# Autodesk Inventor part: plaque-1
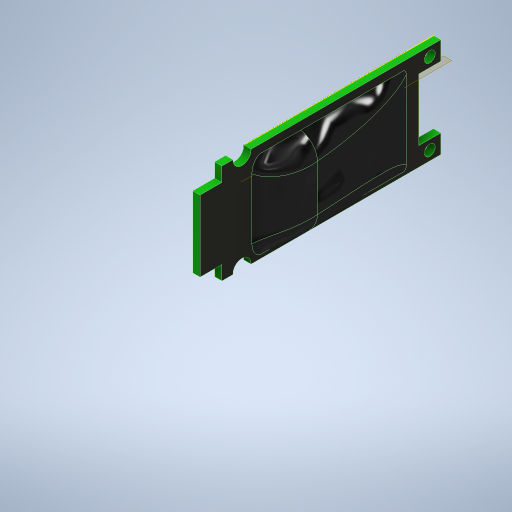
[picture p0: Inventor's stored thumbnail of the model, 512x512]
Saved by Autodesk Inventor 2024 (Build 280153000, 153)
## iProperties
Created: 2024-09
Part Number: plaque-1
Material: Générique
Document SubType Name: Modeling
Designer: bruno
Density: 1 g/cm^3
Appearance: Vert foncé
Author: bruno
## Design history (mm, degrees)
sketch "Esquisse1"
  geometry: L1 (0, 0)-(13.387, 0); L2 (0.487, -30)-(0.487, -27); L3 (11.436, 0)-(6.567, 0); L4 (2.053, 1.609)-(2.053, 4.609); L5 (6.567, 3)-(11.436, 3); L6 (11.436, 3)-(11.436, 0); L7 (10.823, -27)-(6.567, -27); L8 (2.987, -28.609)-(2.987, -30); L9 (10.823, -30)-(10.823, -27); L10 (13.387, -30)-(10.823, -30); L11 (2.987, -30)-(0.487, -30); L12 (13.387, 0)-(13.387, -1.5); L13 (13.387, -3.996)-(13.387, -30); L14 (6.567, 0)-(6.567, -34.615); L15 (6.567, 0)-(6.567, 3); C1 r 0.75 at (12.113, -28.5); A1 r 0.75 centre (1.737, -26.891) between (2.053, -27.57) and (0.995, -27); A2 r 1.25 centre (13.317, -2.748) between (13.387, -1.5) and (13.387, -3.996); 1 further point
  constraints: 30 end point, 7 parallel, 6 point on line, 5 point on circle, 4 perpendicular, 3 centre point, 3 horizontal, 1 vertical
  dimensions: "d1" = 30 distance of L1.end L10.start; "d3" = 3 distance of L4.start L4.end; "d7" = 1.5 diameter of C1; "d8" = 1.5 diameter of A1; "d10" = 2.5 diameter of A2; "d11" = 9 dimension on A1 C1; "d12" = 5.5 distance from line of L14 point (12.067, -2.748); "d13" = 1.5 distance of L1.end L12.end; "d14" = 3 distance between parallel lines of L7 L10; "d15" = 1.5 distance from line of C1.centre L10; "d90" = 6.82 distance between parallel lines of L14 L13
extrude "Extrusion1" new body sketch "Esquisse1" distance "d16" = 1; taper "d17" = 0 deg
mirror "Mise en miroir1"
node "Plan de construction1"
sketch "Esquisse3"
  geometry: L1 (0, 0)-(0, 26.004) reference; L2 (0, 0)-(1, 0) reference; L3 (1, 0)-(1, 26.004) reference; L4 (0, 26.004)-(1, 26.004) reference; L5 (1, 26.004)-(1, 28.5) reference; L6 (1, 25.34)-(1, 4.743); L7 (1, 0)-(1, 26.004) reference; L8 (3, 18.706)-(3, 18.91); A1 r 101.908 centre (-98.658, 26.036) between (1, 4.743) and (3, 18.91); A2 r 9.769 centre (-6.718, 19.907) between (3, 18.91) and (1, 25.895); 2 further points
  constraints: 5 point on circle, 4 end point, 4 point on line, 2 centre point
  dimensions: "d22" = 2 distance from line of L3 L8.start
extrude "Extrusion2" join sketch "Esquisse3" distance "d19" = 12; taper "d20" = 0 deg
fillet "Congé2" dims "d23" = 3
sketch "Esquisse4"
  geometry: L1 (-30, 13.387)-(-3.996, 13.387) reference; L2 (-3.996, 0.834)-(-26.205, 0.834); L3 (-26.205, 0.834)-(-26.205, 13.387); L4 (-26.205, 13.387)-(-3.996, 13.387); L5 (-3.996, 13.387)-(-3.996, 0.834); 1 further point; 1 other entity
  constraints: 1 coincident, 1 point on line, 2 other
  node "Image1"
sketch "Esquisse5"
  geometry: L1 (-10.83, 5.054)-(-19.195, 5.054); L2 (-19.195, 5.054)-(-19.195, 8.454); L3 (-19.195, 8.454)-(-10.83, 8.454); L4 (-10.83, 8.454)-(-10.83, 5.054); 1 further point
  constraints: 8 end point, 2 parallel, 1 horizontal, 1 perpendicular
  dimensions: "d76" = 3.4 distance between parallel lines of L1 L3
extrude "Extrusion3" join sketch "Esquisse5" distance "d65" = 1; taper "d66" = 0 deg
fillet "Congé3" dims "d67" = 0.2
node "Plan de construction2"
sketch "Esquisse6"
  geometry: L1 (-0.8, 3.4)-(-0.8, 0) reference; L2 (-0.8, 3.4)-(-0.467, 3.4); L3 (-0.467, 3.4)-(-0.467, 3.459); L4 (-0.467, 3.607)-(-0.666, 3.607); L5 (-0.525, 3.65)-(-0.295, 3.721); L6 (0, 5.769)-(0, -2.744) reference; L7 (-0.154, 3.751)-(0, 3.751); L8 (0, 3.751)-(0, 3.961); L9 (0, 3.961)-(-0.059, 3.961); L10 (-0.154, 3.961)-(-0.154, 3.912); L11 (-0.21, 3.748)-(-0.154, 3.765); L12 (-0.326, 3.65)-(0, 3.751); L13 (-0.666, 3.459)-(-0.666, 3.4); A1 r 0.2 centre (-0.267, 3.459) between (-0.326, 3.65) and (-0.467, 3.459); A2 r 0.2 centre (-0.466, 3.459) between (-0.525, 3.65) and (-0.666, 3.459); A3 r 0.2 centre (-0.354, 3.912) between (-0.295, 3.721) and (-0.157, 3.878); A4 r 0.1 centre (-0.059, 3.861) between (-0.059, 3.961) and (-0.157, 3.878); 2 further points
  constraints: 22 end point, 10 point on line, 9 point on circle, 8 tangent, 4 centre point, 4 parallel, 3 perpendicular, 2 equal radius, 2 horizontal
  dimensions: "d69" = 0.2 radius of A1; "d70" = 0.1 radius of A4
extrude "Extrusion4" join sketch "Esquisse6" distance "d71" = 0.3; taper "d72" = 0 deg
pattern_linear "Réseau rectangulaire1" dims "d75" = 0.6
node "Plan de construction3"
mirror "Mise en miroir2"
node "Plan de construction4"
sketch "Esquisse7"
  geometry: L1 (-8.637, 9.146)-(-10.123, 9.146); L2 (-10.123, 9.146)-(-10.123, 8.363); L3 (-10.123, 8.363)-(-8.637, 8.363); L4 (-8.637, 8.363)-(-8.637, 9.146); L5 (-8.637, 5.391)-(-10.123, 5.391); L6 (-10.123, 5.391)-(-10.123, 4.64); L7 (-10.123, 4.64)-(-8.637, 4.64); L8 (-8.637, 4.64)-(-8.637, 5.391); L9 (-8.637, 4.112)-(-10.123, 4.112); L10 (-10.123, 4.112)-(-10.123, 3.361); L11 (-10.123, 3.361)-(-8.637, 3.361); L12 (-8.637, 3.361)-(-8.637, 4.112); L13 (-8.637, 2.914)-(-10.123, 2.914); L14 (-10.123, 2.914)-(-10.123, 2.291); L15 (-10.123, 2.291)-(-8.637, 2.291); L16 (-8.637, 2.291)-(-8.637, 2.914); 1 further point
  constraints: 32 end point, 8 parallel, 6 point on line, 4 horizontal, 4 perpendicular
extrude "Extrusion5" join sketch "Esquisse7" distance "d78" = 0.5; taper "d79" = 0 deg
sketch "Esquisse8"
  geometry: L1 (-9.039, 9.258)-(-9.725, 9.258); L2 (-9.725, 9.258)-(-9.725, 2.207); L3 (-9.725, 2.207)-(-9.039, 2.207); L4 (-9.039, 2.207)-(-9.039, 9.258); 1 further point
  constraints: 8 end point, 2 parallel, 1 horizontal, 1 perpendicular
extrude "Extrusion6" cut sketch "Esquisse8" distance "d80" = 0.1; taper "d81" = 0 deg
node "Plan de construction5"
sketch "Esquisse9"
  geometry: L1 (0, 26.004)-(0, 0) reference; L2 (0, 0)-(-0.109, 0); L3 (-0.109, 0)-(-0.109, 1.073); L4 (-0.109, 1.073)-(0, 1.073); L5 (0, 1.073)-(0, 0); L6 (-0.109, 0)-(-0.262, 0); L7 (-0.262, 0)-(-0.109, 0.536); 2 further points
  constraints: 12 end point, 2 horizontal, 2 parallel, 1 midpoint, 1 perpendicular
extrude "Extrusion7" join sketch "Esquisse9" distance "d83" = 1; taper "d84" = 0 deg
fillet "Congé5" dims "d86" = 0.2
pattern_linear "Réseau rectangulaire2" dims "d89" = 2
node "Solide1"
node "Boucle projetée1"
other parameters: "d5" = 3, "d6" = 2.5, "d18" = -0.5, "d68" = -0.5, "d77" = -1.7, "d82" = -3.175
